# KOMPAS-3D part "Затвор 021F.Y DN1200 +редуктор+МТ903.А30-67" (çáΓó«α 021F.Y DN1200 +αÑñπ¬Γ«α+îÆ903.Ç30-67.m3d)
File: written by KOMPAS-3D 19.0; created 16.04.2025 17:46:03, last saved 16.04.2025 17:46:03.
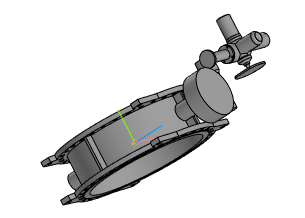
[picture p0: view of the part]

Document properties: Полное имя файла: Затвор 021F.Y DN1200 +редуктор+МТ903.А30-67.a3d

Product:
- Part/product: Затвор 021F.Y DN1200 +редуктор+МТ903.А30-67
    Масса: 1751.91

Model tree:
1. Операция без истории:1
